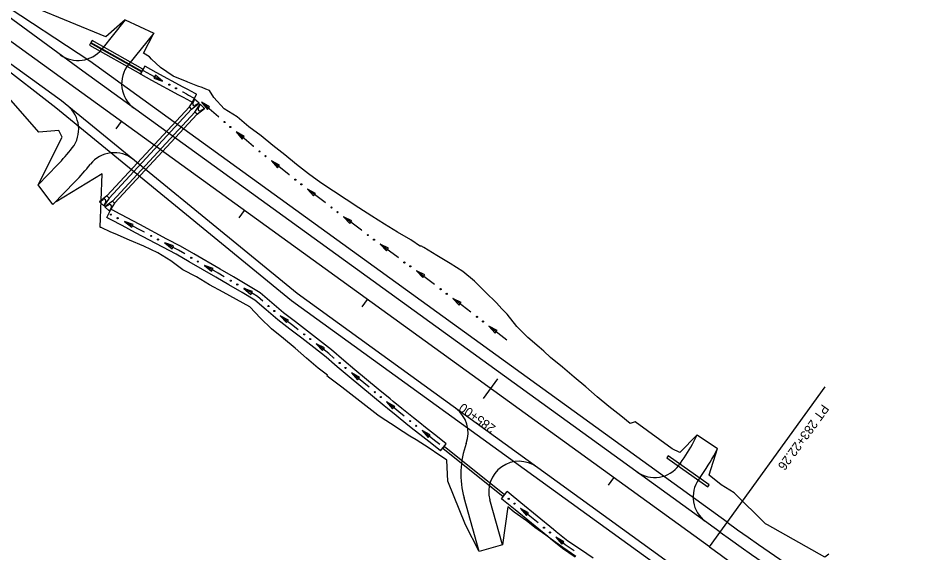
# Model space of a CAD drawing. Extents: x 948761 to 996004, y 1858548 to 1925175.
# Drawn here: x 962143 to 962745, y 1901285 to 1901636 of the extents above; entities that cross this region are included whole.
import ezdxf

# ---------------------------------------------------------------- set-up
doc = ezdxf.new("R2010")
doc.units = 0
for name, color, linetype in [('62', 7, 'Continuous'), ('R_Drainage', 7, 'Continuous'), ('R_Horz Alg', 7, 'Continuous'), ('R_Horz Alg Annot', 7, 'Continuous'), ('R_Proposed Const Limits', 7, 'Continuous'), ('R_Proposed Road', 7, 'Continuous')]:
    doc.layers.add(name, color=color, linetype=linetype)

msp = doc.modelspace()

# ---------------------------------------------------------------- linework, layer by layer
at = {"layer": '62'}
for p, q in [((962225.9, 1901604.85), (962223.01, 1901599.59)), ((962232.85, 1901598.81), (962231.84, 1901596.95)), ((962231.84, 1901596.95), (962237.62, 1901595.02)), ((962237.62, 1901595.02), (962232.85, 1901598.81)), ((962257.17, 1901581.01), (962260.02, 1901586.29)), ((962263.22, 1901581.08), (962267.08, 1901576.36)), ((962268.46, 1901577.97), (962263.22, 1901581.08)), ((962267.08, 1901576.36), (962268.46, 1901577.97)), ((962286.08, 1901561.59), (962289.97, 1901556.9)), ((962291.34, 1901558.51), (962286.08, 1901561.59)), ((962289.97, 1901556.9), (962291.34, 1901558.51)), ((962309.31, 1901542.56), (962313.38, 1901538.01)), ((962314.68, 1901539.68), (962309.31, 1901542.56)), ((962313.38, 1901538.01), (962314.68, 1901539.68)), ((962332.94, 1901524), (962337.02, 1901519.48)), ((962338.32, 1901521.15), (962332.94, 1901524)), ((962337.02, 1901519.48), (962338.32, 1901521.15)), ((962200.8, 1901505.29), (962203.58, 1901510.61)), ((962356.83, 1901505.79), (962360.96, 1901501.32)), ((962362.24, 1901503.01), (962356.83, 1901505.79)), ((962360.96, 1901501.32), (962362.24, 1901503.01)), ((962212.48, 1901502.56), (962217.29, 1901498.81)), ((962218.28, 1901500.68), (962212.48, 1901502.56)), ((962217.29, 1901498.81), (962218.28, 1901500.68)), ((962239.02, 1901488.48), (962243.82, 1901484.73)), ((962244.81, 1901486.6), (962239.02, 1901488.48)), ((962243.82, 1901484.73), (962244.81, 1901486.6)), ((962380.83, 1901487.74), (962385.03, 1901483.32)), ((962386.28, 1901485.02), (962380.83, 1901487.74)), ((962385.03, 1901483.32), (962386.28, 1901485.02)), ((962265.2, 1901473.77), (962269.86, 1901469.84)), ((962270.92, 1901471.67), (962265.2, 1901473.77)), ((962269.86, 1901469.84), (962270.92, 1901471.67)), ((962404.76, 1901470.18), (962408.93, 1901465.74)), ((962410.2, 1901467.44), (962404.76, 1901470.18)), ((962408.93, 1901465.74), (962410.2, 1901467.44)), ((962291.16, 1901458.65), (962295.75, 1901454.65)), ((962296.84, 1901456.46), (962291.16, 1901458.65)), ((962295.75, 1901454.65), (962296.84, 1901456.46)), ((962428.7, 1901452.05), (962432.84, 1901447.58)), ((962434.12, 1901449.26), (962428.7, 1901452.05)), ((962432.84, 1901447.58), (962434.12, 1901449.26)), ((962315.01, 1901440.54), (962319.15, 1901436.07)), ((962320.43, 1901437.76), (962315.01, 1901440.54)), ((962319.15, 1901436.07), (962320.43, 1901437.76)), ((962452.53, 1901433.75), (962456.58, 1901429.2)), ((962457.89, 1901430.86), (962452.53, 1901433.75)), ((962456.58, 1901429.2), (962457.89, 1901430.86)), ((962338.83, 1901422.24), (962342.92, 1901417.73)), ((962344.22, 1901419.4), (962338.83, 1901422.24)), ((962342.92, 1901417.73), (962344.22, 1901419.4)), ((962361.95, 1901403.08), (962365.91, 1901398.45)), ((962367.26, 1901400.09), (962361.95, 1901403.08)), ((962365.91, 1901398.45), (962367.26, 1901400.09)), ((962385.15, 1901384), (962389.11, 1901379.37)), ((962390.45, 1901381.01), (962385.15, 1901384)), ((962389.11, 1901379.37), (962390.45, 1901381.01)), ((962408.5, 1901365.11), (962412.55, 1901360.56)), ((962413.87, 1901362.22), (962408.5, 1901365.11)), ((962412.55, 1901360.56), (962413.87, 1901362.22)), ((962420.69, 1901351.65), (962424.41, 1901356.35)), ((962460.75, 1901320.18), (962464.47, 1901324.88)), ((962473.29, 1901313.84), (962477.27, 1901309.23)), ((962478.61, 1901310.87), (962473.29, 1901313.84)), ((962477.27, 1901309.23), (962478.61, 1901310.87)), ((962496.57, 1901294.86), (962500.55, 1901290.25)), ((962501.89, 1901291.89), (962496.57, 1901294.86)), ((962500.55, 1901290.25), (962501.89, 1901291.89))]:
    msp.add_line(p, q, dxfattribs=at)
for points in [[(962257.17, 1901581.01), (962257.14, 1901581.02), (962256.91, 1901581.15), (962256.64, 1901581.29), (962253.33, 1901583.09), (962251.82, 1901583.91), (962248.65, 1901585.63), (962248.27, 1901585.83), (962230.54, 1901595.45), (962223.47, 1901599.34), (962223.01, 1901599.59)], [(962224.45, 1901602.22), (962224.91, 1901601.97), (962231.97, 1901598.08), (962237.62, 1901595.02)], [(962260.02, 1901586.29), (962260, 1901586.3), (962259.77, 1901586.42), (962259.5, 1901586.57), (962256.19, 1901588.36), (962254.68, 1901589.18), (962251.51, 1901590.9), (962251.13, 1901591.11), (962233.41, 1901600.71), (962226.36, 1901604.59), (962225.9, 1901604.85)], [(962250.8, 1901587.87), (962250.84, 1901587.86)], [(962250.84, 1901587.86), (962253.25, 1901586.55), (962254.76, 1901585.73), (962258.07, 1901583.93), (962258.34, 1901583.79), (962258.57, 1901583.66), (962258.59, 1901583.65)], [(962274.63, 1901571.34), (962274.45, 1901571.49), (962266.81, 1901577.99), (962264.53, 1901579.96), (962263.22, 1901581.08)], [(962274.66, 1901571.31), (962274.63, 1901571.34)], [(962297.51, 1901551.87), (962297.37, 1901551.99), (962289.73, 1901558.49), (962286.08, 1901561.59)], [(962297.54, 1901551.85), (962297.51, 1901551.87)], [(962321.1, 1901533.28), (962320.95, 1901533.4), (962313.08, 1901539.59), (962309.31, 1901542.56)], [(962321.13, 1901533.26), (962321.1, 1901533.28)], [(962344.85, 1901514.88), (962344.68, 1901515.02), (962336.71, 1901521.06), (962332.94, 1901524)], [(962424.41, 1901356.35), (962418.57, 1901360.97), (962410.73, 1901367.18), (962406.99, 1901370.14), (962402.89, 1901373.38), (962395.13, 1901379.67), (962389.52, 1901384.29), (962387.4, 1901386.03), (962379.66, 1901392.4), (962364.2, 1901405.12), (962356.89, 1901411.22), (962348.85, 1901418.26), (962340.98, 1901424.37), (962333.07, 1901430.51), (962325.13, 1901436.63), (962317.22, 1901442.63), (962309.64, 1901449.07), (962301.82, 1901455.73), (962293, 1901461.05), (962284.32, 1901466.15), (962275.61, 1901471.19), (962258.22, 1901481.28), (962249.47, 1901486.33), (962240.5, 1901491.09), (962222.66, 1901500.55), (962213.74, 1901505.29), (962211.05, 1901506.7), (962209.26, 1901507.63), (962204.78, 1901509.98), (962204.54, 1901510.1), (962204.27, 1901510.24), (962203.58, 1901510.61)], [(962344.88, 1901514.86), (962344.85, 1901514.88)], [(962420.69, 1901351.65), (962414.85, 1901356.26), (962407, 1901362.48), (962403.27, 1901365.43), (962399.14, 1901368.7), (962391.34, 1901375.03), (962385.71, 1901379.65), (962383.59, 1901381.4), (962375.85, 1901387.76), (962360.37, 1901400.5), (962352.66, 1901406.94), (962350.83, 1901408.49), (962345.23, 1901413.47), (962337.3, 1901419.63), (962329.4, 1901425.77), (962321.49, 1901431.86), (962313.46, 1901437.95), (962305.75, 1901444.5), (962298.3, 1901450.84), (962289.93, 1901455.89), (962281.29, 1901460.96), (962272.6, 1901466), (962255.22, 1901476.09), (962246.56, 1901481.08), (962237.69, 1901485.79), (962219.85, 1901495.25), (962210.94, 1901499.98), (962208.26, 1901501.38), (962206.47, 1901502.32), (962202, 1901504.66), (962201.77, 1901504.78), (962201.5, 1901504.92), (962200.8, 1901505.29)], [(962368.77, 1901496.72), (962368.58, 1901496.87), (962360.61, 1901502.92), (962356.83, 1901505.79)], [(962225.73, 1901495.53), (962221.26, 1901497.9), (962212.48, 1901502.56)], [(962225.77, 1901495.51), (962225.73, 1901495.53)], [(962368.8, 1901496.7), (962368.77, 1901496.72)], [(962252.18, 1901481.3), (962248.01, 1901483.71), (962239.09, 1901488.44), (962239.02, 1901488.48)], [(962392.88, 1901478.81), (962392.66, 1901478.98), (962384.62, 1901484.93), (962380.83, 1901487.74)], [(962252.22, 1901481.28), (962252.18, 1901481.3)], [(962392.91, 1901478.78), (962392.88, 1901478.81)], [(962278.17, 1901466.24), (962274.11, 1901468.6), (962265.42, 1901473.64), (962265.2, 1901473.77)], [(962416.73, 1901461.14), (962408.8, 1901467.16), (962404.76, 1901470.18)], [(962278.21, 1901466.22), (962278.17, 1901466.24)], [(962416.76, 1901461.12), (962416.73, 1901461.14)], [(962303.57, 1901450.3), (962300.06, 1901453.29), (962291.47, 1901458.47), (962291.16, 1901458.65)], [(962303.6, 1901450.28), (962303.57, 1901450.3)], [(962440.65, 1901442.97), (962434.88, 1901447.36), (962432.7, 1901449.02), (962428.7, 1901452.05)], [(962440.68, 1901442.95), (962440.66, 1901442.97), (962440.65, 1901442.97)], [(962326.94, 1901431.45), (962323.31, 1901434.24), (962315.34, 1901440.29), (962315.02, 1901440.56)], [(962326.97, 1901431.43), (962326.94, 1901431.45)], [(962464.3, 1901424.45), (962456.44, 1901430.66), (962452.71, 1901433.61), (962452.53, 1901433.75)], [(962350.48, 1901412.81), (962347.04, 1901415.86), (962339.14, 1901422), (962338.83, 1901422.24)], [(962350.51, 1901412.78), (962350.48, 1901412.81)], [(962373.53, 1901393.55), (962370.02, 1901396.44), (962362.28, 1901402.81), (962361.95, 1901403.09)], [(962373.56, 1901393.53), (962373.53, 1901393.55)], [(962396.75, 1901374.5), (962393.24, 1901377.35), (962387.62, 1901381.97), (962385.5, 1901383.71), (962385.15, 1901384)], [(962396.78, 1901374.47), (962396.75, 1901374.5)], [(962420.27, 1901355.8), (962416.71, 1901358.62), (962408.86, 1901364.83), (962408.5, 1901365.11)], [(962521.04, 1901281.22), (962512.72, 1901286.78), (962504.51, 1901292.26), (962496.86, 1901298.5), (962495.1, 1901299.93), (962473.57, 1901317.49), (962465.79, 1901323.84), (962464.47, 1901324.88)], [(962509.39, 1901281.79), (962500.94, 1901287.43), (962493.07, 1901293.85), (962491.31, 1901295.28), (962469.78, 1901312.84), (962462.03, 1901319.16), (962460.75, 1901320.18)], [(962484.92, 1901304.36), (962479.44, 1901308.83), (962473.29, 1901313.84)], [(962484.95, 1901304.34), (962484.92, 1901304.36)], [(962508.6, 1901285.93), (962502.73, 1901289.84), (962496.57, 1901294.86)], [(962508.63, 1901285.9), (962508.6, 1901285.93)]]:
    msp.add_lwpolyline(points, dxfattribs=at)
for centre in [(962242.03, 1901592.67), (962246.44, 1901590.28), (962278.43, 1901568.05), (962282.25, 1901564.81), (962301.43, 1901548.73), (962305.36, 1901545.62), (962325.03, 1901530.14), (962328.96, 1901527.05), (962348.83, 1901511.82), (962352.82, 1901508.79), (962203.59, 1901507.17), (962208.03, 1901504.85), (962230.15, 1901493.14), (962234.58, 1901490.79), (962372.78, 1901493.69), (962376.79, 1901490.69), (962256.52, 1901478.76), (962260.85, 1901476.25), (962396.81, 1901475.68), (962400.73, 1901473.15), (962282.5, 1901463.69), (962286.82, 1901461.15), (962420.71, 1901458.08), (962424.7, 1901455.04), (962307.37, 1901447.02), (962311.18, 1901443.77), (962444.61, 1901439.88), (962448.58, 1901436.82), (962330.9, 1901428.36), (962334.85, 1901425.28), (962354.24, 1901409.48), (962358.09, 1901406.27), (962377.39, 1901390.34), (962381.26, 1901387.15), (962400.63, 1901371.3), (962404.56, 1901368.19), (962465.51, 1901320.15), (962469.39, 1901316.98), (962488.79, 1901301.16), (962492.67, 1901298)]:
    msp.add_circle(centre, 0.375, dxfattribs=at)
at = {"layer": 'R_Drainage'}
for p, q in [((962190.2, 1901619.98), (962189.47, 1901618.67)), ((962189.47, 1901618.67), (962222.98, 1901599.86)), ((962223.72, 1901601.16), (962190.2, 1901619.98)), ((962191.18, 1901621.73), (962190.45, 1901620.42)), ((962190.45, 1901620.42), (962223.96, 1901601.6)), ((962224.7, 1901602.91), (962191.18, 1901621.73)), ((962222.98, 1901599.86), (962223.72, 1901601.16)), ((962223.96, 1901601.6), (962224.7, 1901602.91)), ((962255.25, 1901577.97), (962258.68, 1901583.13)), ((962258.68, 1901583.13), (962257.43, 1901580.48)), ((962261.61, 1901580.41), (962258.68, 1901583.13)), ((962200.92, 1901519.42), (962255.25, 1901577.97)), ((962202.39, 1901518.06), (962256.72, 1901576.61)), ((962256.72, 1901576.61), (962255.25, 1901577.97)), ((962256.72, 1901576.61), (962261.61, 1901580.41)), ((962258.92, 1901574.57), (962262.35, 1901579.73)), ((962261.61, 1901580.41), (962259.06, 1901578.97)), ((962260.38, 1901573.21), (962265.28, 1901577.01)), ((962262.35, 1901579.73), (962261.09, 1901577.08)), ((962265.28, 1901577.01), (962262.35, 1901579.73)), ((962265.28, 1901577.01), (962262.72, 1901575.57)), ((962204.59, 1901516.02), (962258.92, 1901574.57)), ((962206.05, 1901514.66), (962260.38, 1901573.21)), ((962260.38, 1901573.21), (962258.92, 1901574.57)), ((962200.92, 1901519.42), (962196.03, 1901515.61)), ((962196.03, 1901515.61), (962198.58, 1901517.06)), ((962196.03, 1901515.61), (962198.96, 1901512.89)), ((962202.39, 1901518.06), (962198.96, 1901512.89)), ((962198.96, 1901512.89), (962200.21, 1901515.55)), ((962204.59, 1901516.02), (962199.69, 1901512.21)), ((962200.92, 1901519.42), (962202.39, 1901518.06)), ((962204.59, 1901516.02), (962206.05, 1901514.66)), ((962199.69, 1901512.21), (962202.25, 1901513.66)), ((962199.69, 1901512.21), (962202.62, 1901509.49)), ((962206.05, 1901514.66), (962202.62, 1901509.49)), ((962202.62, 1901509.49), (962203.88, 1901512.15)), ((962423.01, 1901354.58), (962422.07, 1901353.4)), ((962422.07, 1901353.4), (962461.87, 1901321.64)), ((962462.81, 1901322.81), (962423.01, 1901354.58)), ((962570.59, 1901348.44), (962569.72, 1901347.22)), ((962569.72, 1901347.22), (962596.57, 1901328.15)), ((962597.44, 1901329.38), (962570.59, 1901348.44)), ((962596.57, 1901328.15), (962597.44, 1901329.38)), ((962461.87, 1901321.64), (962462.81, 1901322.81))]:
    msp.add_line(p, q, dxfattribs=at)
for centre, start, end in [((962258.48, 1901579.98), 154.67052, 299.61067), ((962262.14, 1901576.58), 154.67052, 299.61067), ((962199.16, 1901516.05), 334.67052, 119.61067), ((962202.83, 1901512.65), 334.67052, 119.61067)]:
    msp.add_arc(centre, 1.17, start, end, dxfattribs=at)
at = {"layer": 'R_Horz Alg'}
msp.add_line((962597.7, 1901288.53), (961643.19, 1901978.45), dxfattribs=at)
msp.add_arc((963492.74, 1902526.81), 1527.89, 234.14059, 254.62332, dxfattribs=at)
at = {"layer": 'R_Horz Alg Annot'}
for points in [[(962207, 1901563.53), (962210.51, 1901568.39)], [(962288.04, 1901504.95), (962291.56, 1901509.81)], [(962369.09, 1901446.37), (962372.6, 1901451.23)], [(962448.96, 1901386.17), (962458.34, 1901399.13)], [(962597.7, 1901288.53), (962673.86, 1901393.89)], [(962531.18, 1901329.21), (962534.7, 1901334.07)]]:
    msp.add_lwpolyline(points, dxfattribs=at)
at = {"layer": 'R_Proposed Const Limits'}
for points in [[(962213.04, 1901635.21), (962200.23, 1901624.18), (962106.05, 1901662.86)], [(962169.3, 1901562.58), (962156.06, 1901561.33), (962088.44, 1901638.49)], [(962470.89, 1901433.58), (962464.4, 1901441.66), (962461.08, 1901445.2), (962457.39, 1901449.04), (962450.23, 1901456.2), (962445, 1901461.35), (962443.03, 1901463.31), (962435.32, 1901469.71), (962426.87, 1901475.1), (962418.18, 1901480.15), (962409.68, 1901485.46), (962407.68, 1901486.55), (962407.48, 1901486.28), (962400.99, 1901490.51), (962392.29, 1901495.54), (962383.79, 1901500.84), (962375.34, 1901506.23), (962366.88, 1901511.59), (962358.56, 1901517.15), (962350.17, 1901522.62), (962341.73, 1901528.01), (962333.65, 1901533.9), (962325.86, 1901540.19), (962318.03, 1901546.43), (962310.23, 1901552.71), (962302.5, 1901559.09), (962294.38, 1901564.92), (962286.78, 1901571.48), (962278.19, 1901576.66), (962271.29, 1901584.19), (962268.45, 1901588.79), (962266.05, 1901589.75), (962263.66, 1901590.7), (962260.72, 1901591.77), (962254.16, 1901594.28), (962253.76, 1901594.44), (962244.48, 1901598.31), (962236.23, 1901603.97), (962230.39, 1901609.54), (962229.02, 1901611.07), (962225.06, 1901613.46), (962231.79, 1901626.61)], [(962155.72, 1901526.71), (962171.5, 1901558.21), (962169.3, 1901562.58)], [(962196.57, 1901498.85), (962197.79, 1901534.01), (962167.44, 1901515.49)], [(962446, 1901285.57), (962437.03, 1901303.1), (962425.42, 1901331.78), (962424.75, 1901345.61), (962421.34, 1901347.94), (962419.46, 1901349.21), (962413.06, 1901353.56), (962404.56, 1901358.87), (962400.46, 1901361.32), (962396.12, 1901364.27), (962387.74, 1901369.75), (962381.59, 1901373.63), (962379.37, 1901375.23), (962371.47, 1901381.37), (962363.62, 1901387.59), (962355.62, 1901393.59), (962347.66, 1901399.65), (962345.84, 1901400.99), (962345.84, 1901400.99), (962346.24, 1901401.56), (962340.02, 1901406.16), (962332.36, 1901412.62), (962324.84, 1901419.29), (962317.17, 1901425.74), (962309.27, 1901431.9), (962302.14, 1901439.09), (962295.09, 1901446.42), (962286.28, 1901451.3), (962277.42, 1901456.11), (962268.57, 1901460.93), (962260, 1901466.15), (962251.04, 1901470.82), (962243.02, 1901476.79), (962234.53, 1901482.11), (962225.26, 1901486.36), (962215.85, 1901490.42), (962206.47, 1901494.52), (962203.55, 1901495.59), (962197.06, 1901498.57), (962196.83, 1901498.7), (962196.57, 1901498.85)], [(962589.68, 1901362.2), (962578.12, 1901350.72), (962573.07, 1901353.02), (962565, 1901358.93), (962556.93, 1901364.83), (962548.88, 1901370.77), (962545.4, 1901369.81), (962539.38, 1901374.69), (962531.5, 1901380.86), (962523.81, 1901387.29), (962516.22, 1901393.87), (962508.54, 1901400.31), (962500.84, 1901406.73), (962493.14, 1901413.15), (962488.75, 1901417.31), (962485.67, 1901419.87), (962478.04, 1901426.39), (962476.43, 1901428.02), (962470.89, 1901433.58)], [(962613.91, 1901324.16), (962605.38, 1901329.43), (962597.59, 1901335.74), (962597.48, 1901335.87), (962603.07, 1901353.28)], [(962676.24, 1901283.85), (962673.72, 1901281.75), (962635.89, 1901302.97), (962634.58, 1901303.63), (962613.91, 1901324.16)], [(962509.82, 1901282.27), (962501.15, 1901288.18), (962493.42, 1901293.56), (962489.95, 1901296.17), (962482.75, 1901301.32), (962477.19, 1901305.74), (962469.1, 1901311.38), (962464.96, 1901314.87), (962461.4, 1901289.9)]]:
    msp.add_lwpolyline(points, dxfattribs=at)
at = {"layer": 'R_Proposed Road'}
for p, q in [((962185.12, 1901601.55), (962104.22, 1901660.33)), ((962189.81, 1901608.03), (962106.05, 1901662.86)), ((962167.26, 1901577.45), (962088.44, 1901638.49)), ((962171.06, 1901582.1), (962089.81, 1901640.39)), ((962213.04, 1901635.21), (962197.56, 1901616)), ((962213.04, 1901635.21), (962231.79, 1901626.61)), ((962231.79, 1901626.61), (962215.08, 1901605.87)), ((962609.42, 1901304.74), (962189.81, 1901608.03)), ((962604.73, 1901298.25), (962185.12, 1901601.55)), ((962326.13, 1901455.21), (962171.06, 1901582.1)), ((962322.47, 1901450.45), (962167.26, 1901577.45)), ((962168.48, 1901539.95), (962155.72, 1901526.71)), ((962180, 1901528.85), (962165.42, 1901513.71)), ((962165.42, 1901513.71), (962155.72, 1901526.71)), ((962583.64, 1901269.08), (962326.13, 1901455.21)), ((962580.13, 1901264.21), (962322.47, 1901450.45)), ((962587.47, 1901357.96), (962589.68, 1901362.2)), ((962589.68, 1901362.2), (962603.07, 1901353.28)), ((962601.65, 1901350.56), (962603.07, 1901353.28)), ((962578.57, 1901343.56), (962577.75, 1901342.43)), ((962591.54, 1901334.18), (962590.72, 1901333.06)), ((962446, 1901285.57), (962436.12, 1901320.7)), ((962461.4, 1901289.9), (962453.1, 1901319.43)), ((962461.4, 1901289.9), (962446, 1901285.57))]:
    msp.add_line(p, q, dxfattribs=at)
for centre, radius, start, end in [((962181.98, 1901628.55), 20, 233.99825, 321.14059), ((962230.65, 1901593.32), 20, 141.14059, 234.14059), ((962162.36, 1901563.37), 20, 322.01206, 50.70696), ((962066.21, 1901638.46), 142, 316.07053, 322.01206), ((962205.71, 1901527.9), 20, 50.70696, 141.60143), ((962066.21, 1901638.46), 158, 316.07053, 321.60143), ((962418.83, 1901363.53), 20, 339.6458, 54.14059), ((962491.96, 1901336.4), 58, 159.6458, 195.70254), ((962483.75, 1901412.1), 117, 324.14059, 332.44144), ((962483.75, 1901412.1), 133, 324.14059, 332.44144), ((962472.35, 1901324.84), 20, 54.1406, 195.70254), ((962561.55, 1901354.15), 20, 234.14059, 324.14059), ((962606.93, 1901321.34), 20, 144.14059, 234.14059), ((963492.74, 1902526.81), 1507.89, 234.14059, 254.62332), ((963492.74, 1902526.81), 1515.89, 234.14059, 254.62332)]:
    msp.add_arc(centre, radius, start, end, dxfattribs=at)

# ---------------------------------------------------------------- texts
at = {"layer": 'R_Horz Alg'}
msp.add_text('+', height=1, rotation=144.14059, dxfattribs=at).set_placement((962598, 1901288.93))
msp.add_text('+', height=1, rotation=144.14059, dxfattribs=at).set_placement((962598, 1901288.93))
at = {"layer": 'R_Horz Alg Annot'}
for s, rotation, p in [('285+00', 144.14059, (962457.41, 1901367.72)), ('PT 283+22.26', 234.14059, (962672.05, 1901382.85))]:
    msp.add_text(s, height=6, rotation=rotation, dxfattribs=at).set_placement(p)

doc.saveas('drawing.dxf')
